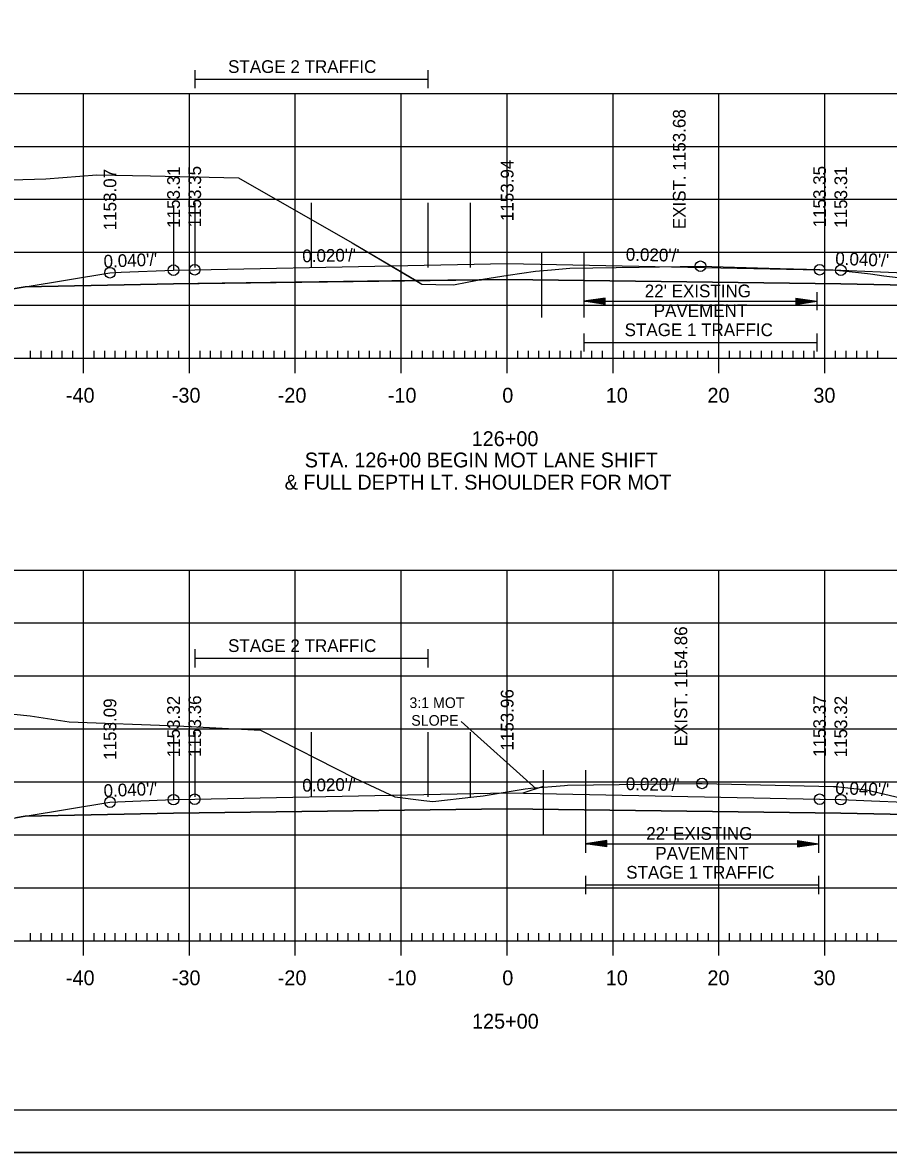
# Model space of a CAD drawing. Extents: x 1322838 to 1324533, y 339903 to 351025.
# Drawn here: x 1323658 to 1323739.7, y 341396.5 to 341503.2 of the extents above; entities that cross this region are included whole.
import ezdxf

# ---------------------------------------------------------------- set-up
doc = ezdxf.new("R2010")
doc.units = 0
for name, color, linetype in [('R_Alt Surface', 7, 'Continuous'), ('R_Axis', 7, 'Continuous'), ('R_Axis Annot', 7, 'Continuous'), ('R_Border', 7, 'Continuous'), ('R_Exist Surface', 7, 'Continuous'), ('R_Fin Surface', 7, 'Continuous'), ('R_Fin Surface Annot', 7, 'Continuous'), ('R_Grid', 7, 'Continuous'), ('R_MOT', 7, 'Continuous'), ('R_No Plot', 7, 'Continuous'), ('R_Xsect Elev', 7, 'Continuous')]:
    doc.layers.add(name, color=color, linetype=linetype)

msp = doc.modelspace()

# ---------------------------------------------------------------- linework, layer by layer
at = {"layer": 'R_Alt Surface'}
for points in [[(1323658.22, 341478.2), (1323672.22, 341478.48), (1323703.72, 341478.91), (1323735.22, 341478.48), (1323749.21, 341478.2)], [(1323658.22, 341428.22), (1323672.22, 341428.5), (1323703.72, 341428.92), (1323735.22, 341428.5), (1323749.21, 341428.22)]]:
    msp.add_lwpolyline(points, dxfattribs=at)
at = {"layer": 'R_Axis'}
for p, q in [((1323663.72, 341470.07), (1323663.72, 341472.87)), ((1323673.72, 341470.07), (1323673.72, 341472.87)), ((1323683.72, 341470.07), (1323683.72, 341472.87)), ((1323693.72, 341470.07), (1323693.72, 341472.87)), ((1323703.72, 341470.07), (1323703.72, 341472.87)), ((1323713.72, 341470.07), (1323713.72, 341472.87)), ((1323723.72, 341470.07), (1323723.72, 341472.87)), ((1323733.72, 341470.07), (1323733.72, 341472.87)), ((1323563.72, 341471.47), (1323843.72, 341471.47)), ((1323658.72, 341471.47), (1323658.72, 341472.17)), ((1323659.72, 341471.47), (1323659.72, 341472.17)), ((1323660.72, 341471.47), (1323660.72, 341472.17)), ((1323661.72, 341471.47), (1323661.72, 341472.17)), ((1323662.72, 341471.47), (1323662.72, 341472.17)), ((1323664.72, 341471.47), (1323664.72, 341472.17)), ((1323665.72, 341471.47), (1323665.72, 341472.17)), ((1323666.72, 341471.47), (1323666.72, 341472.17)), ((1323667.72, 341471.47), (1323667.72, 341472.17)), ((1323668.72, 341471.47), (1323668.72, 341472.17)), ((1323669.72, 341471.47), (1323669.72, 341472.17)), ((1323670.72, 341471.47), (1323670.72, 341472.17)), ((1323671.72, 341471.47), (1323671.72, 341472.17)), ((1323672.72, 341471.47), (1323672.72, 341472.17)), ((1323674.72, 341471.47), (1323674.72, 341472.17)), ((1323675.72, 341471.47), (1323675.72, 341472.17)), ((1323676.72, 341471.47), (1323676.72, 341472.17)), ((1323677.72, 341471.47), (1323677.72, 341472.17)), ((1323678.72, 341471.47), (1323678.72, 341472.17)), ((1323679.72, 341471.47), (1323679.72, 341472.17)), ((1323680.72, 341471.47), (1323680.72, 341472.17)), ((1323681.72, 341471.47), (1323681.72, 341472.17)), ((1323682.72, 341471.47), (1323682.72, 341472.17)), ((1323684.72, 341471.47), (1323684.72, 341472.17)), ((1323685.72, 341471.47), (1323685.72, 341472.17)), ((1323686.72, 341471.47), (1323686.72, 341472.17)), ((1323687.72, 341471.47), (1323687.72, 341472.17)), ((1323688.72, 341471.47), (1323688.72, 341472.17)), ((1323689.72, 341471.47), (1323689.72, 341472.17)), ((1323690.72, 341471.47), (1323690.72, 341472.17)), ((1323691.72, 341471.47), (1323691.72, 341472.17)), ((1323692.72, 341471.47), (1323692.72, 341472.17)), ((1323694.72, 341471.47), (1323694.72, 341472.17)), ((1323695.72, 341471.47), (1323695.72, 341472.17)), ((1323696.72, 341471.47), (1323696.72, 341472.17)), ((1323697.72, 341471.47), (1323697.72, 341472.17)), ((1323698.72, 341471.47), (1323698.72, 341472.17)), ((1323699.72, 341471.47), (1323699.72, 341472.17)), ((1323700.72, 341471.47), (1323700.72, 341472.17)), ((1323701.72, 341471.47), (1323701.72, 341472.17)), ((1323702.72, 341471.47), (1323702.72, 341472.17)), ((1323704.72, 341471.47), (1323704.72, 341472.17)), ((1323705.72, 341471.47), (1323705.72, 341472.17)), ((1323706.72, 341471.47), (1323706.72, 341472.17)), ((1323707.72, 341471.47), (1323707.72, 341472.17)), ((1323708.72, 341471.47), (1323708.72, 341472.17)), ((1323709.72, 341471.47), (1323709.72, 341472.17)), ((1323710.72, 341471.47), (1323710.72, 341472.17)), ((1323711.72, 341471.47), (1323711.72, 341472.17)), ((1323712.72, 341471.47), (1323712.72, 341472.17)), ((1323714.72, 341471.47), (1323714.72, 341472.17)), ((1323715.72, 341471.47), (1323715.72, 341472.17)), ((1323716.72, 341471.47), (1323716.72, 341472.17)), ((1323717.72, 341471.47), (1323717.72, 341472.17)), ((1323718.72, 341471.47), (1323718.72, 341472.17)), ((1323719.72, 341471.47), (1323719.72, 341472.17)), ((1323720.72, 341471.47), (1323720.72, 341472.17)), ((1323721.72, 341471.47), (1323721.72, 341472.17)), ((1323722.72, 341471.47), (1323722.72, 341472.17)), ((1323724.72, 341471.47), (1323724.72, 341472.17)), ((1323725.72, 341471.47), (1323725.72, 341472.17)), ((1323726.72, 341471.47), (1323726.72, 341472.17)), ((1323727.72, 341471.47), (1323727.72, 341472.17)), ((1323728.72, 341471.47), (1323728.72, 341472.17)), ((1323729.72, 341471.47), (1323729.72, 341472.17)), ((1323730.72, 341471.47), (1323730.72, 341472.17)), ((1323731.72, 341471.47), (1323731.72, 341472.17)), ((1323732.72, 341471.47), (1323732.72, 341472.17)), ((1323734.72, 341471.47), (1323734.72, 341472.17)), ((1323735.72, 341471.47), (1323735.72, 341472.17)), ((1323736.72, 341471.47), (1323736.72, 341472.17)), ((1323737.72, 341471.47), (1323737.72, 341472.17)), ((1323738.72, 341471.47), (1323738.72, 341472.17)), ((1323658.72, 341416.47), (1323658.72, 341417.17)), ((1323659.72, 341416.47), (1323659.72, 341417.17)), ((1323660.72, 341416.47), (1323660.72, 341417.17)), ((1323661.72, 341416.47), (1323661.72, 341417.17)), ((1323662.72, 341416.47), (1323662.72, 341417.17)), ((1323663.72, 341415.07), (1323663.72, 341417.87)), ((1323664.72, 341416.47), (1323664.72, 341417.17)), ((1323665.72, 341416.47), (1323665.72, 341417.17)), ((1323666.72, 341416.47), (1323666.72, 341417.17)), ((1323667.72, 341416.47), (1323667.72, 341417.17)), ((1323668.72, 341416.47), (1323668.72, 341417.17)), ((1323669.72, 341416.47), (1323669.72, 341417.17)), ((1323670.72, 341416.47), (1323670.72, 341417.17)), ((1323671.72, 341416.47), (1323671.72, 341417.17)), ((1323672.72, 341416.47), (1323672.72, 341417.17)), ((1323673.72, 341415.07), (1323673.72, 341417.87)), ((1323674.72, 341416.47), (1323674.72, 341417.17)), ((1323675.72, 341416.47), (1323675.72, 341417.17)), ((1323676.72, 341416.47), (1323676.72, 341417.17)), ((1323677.72, 341416.47), (1323677.72, 341417.17)), ((1323678.72, 341416.47), (1323678.72, 341417.17)), ((1323679.72, 341416.47), (1323679.72, 341417.17)), ((1323680.72, 341416.47), (1323680.72, 341417.17)), ((1323681.72, 341416.47), (1323681.72, 341417.17)), ((1323682.72, 341416.47), (1323682.72, 341417.17)), ((1323683.72, 341415.07), (1323683.72, 341417.87)), ((1323684.72, 341416.47), (1323684.72, 341417.17)), ((1323685.72, 341416.47), (1323685.72, 341417.17)), ((1323686.72, 341416.47), (1323686.72, 341417.17)), ((1323687.72, 341416.47), (1323687.72, 341417.17)), ((1323688.72, 341416.47), (1323688.72, 341417.17)), ((1323689.72, 341416.47), (1323689.72, 341417.17)), ((1323690.72, 341416.47), (1323690.72, 341417.17)), ((1323691.72, 341416.47), (1323691.72, 341417.17)), ((1323692.72, 341416.47), (1323692.72, 341417.17)), ((1323693.72, 341415.07), (1323693.72, 341417.87)), ((1323694.72, 341416.47), (1323694.72, 341417.17)), ((1323695.72, 341416.47), (1323695.72, 341417.17)), ((1323696.72, 341416.47), (1323696.72, 341417.17)), ((1323697.72, 341416.47), (1323697.72, 341417.17)), ((1323698.72, 341416.47), (1323698.72, 341417.17)), ((1323699.72, 341416.47), (1323699.72, 341417.17)), ((1323700.72, 341416.47), (1323700.72, 341417.17)), ((1323701.72, 341416.47), (1323701.72, 341417.17)), ((1323702.72, 341416.47), (1323702.72, 341417.17)), ((1323703.72, 341415.07), (1323703.72, 341417.87)), ((1323704.72, 341416.47), (1323704.72, 341417.17)), ((1323705.72, 341416.47), (1323705.72, 341417.17)), ((1323706.72, 341416.47), (1323706.72, 341417.17)), ((1323707.72, 341416.47), (1323707.72, 341417.17)), ((1323708.72, 341416.47), (1323708.72, 341417.17)), ((1323709.72, 341416.47), (1323709.72, 341417.17)), ((1323710.72, 341416.47), (1323710.72, 341417.17)), ((1323711.72, 341416.47), (1323711.72, 341417.17)), ((1323712.72, 341416.47), (1323712.72, 341417.17)), ((1323713.72, 341415.07), (1323713.72, 341417.87)), ((1323714.72, 341416.47), (1323714.72, 341417.17)), ((1323715.72, 341416.47), (1323715.72, 341417.17)), ((1323716.72, 341416.47), (1323716.72, 341417.17)), ((1323717.72, 341416.47), (1323717.72, 341417.17)), ((1323718.72, 341416.47), (1323718.72, 341417.17)), ((1323719.72, 341416.47), (1323719.72, 341417.17)), ((1323720.72, 341416.47), (1323720.72, 341417.17)), ((1323721.72, 341416.47), (1323721.72, 341417.17)), ((1323722.72, 341416.47), (1323722.72, 341417.17)), ((1323723.72, 341415.07), (1323723.72, 341417.87)), ((1323724.72, 341416.47), (1323724.72, 341417.17)), ((1323725.72, 341416.47), (1323725.72, 341417.17)), ((1323726.72, 341416.47), (1323726.72, 341417.17)), ((1323727.72, 341416.47), (1323727.72, 341417.17)), ((1323728.72, 341416.47), (1323728.72, 341417.17)), ((1323729.72, 341416.47), (1323729.72, 341417.17)), ((1323730.72, 341416.47), (1323730.72, 341417.17)), ((1323731.72, 341416.47), (1323731.72, 341417.17)), ((1323732.72, 341416.47), (1323732.72, 341417.17)), ((1323733.72, 341415.07), (1323733.72, 341417.87)), ((1323734.72, 341416.47), (1323734.72, 341417.17)), ((1323735.72, 341416.47), (1323735.72, 341417.17)), ((1323736.72, 341416.47), (1323736.72, 341417.17)), ((1323737.72, 341416.47), (1323737.72, 341417.17)), ((1323738.72, 341416.47), (1323738.72, 341417.17)), ((1323563.72, 341416.47), (1323843.72, 341416.47))]:
    msp.add_line(p, q, dxfattribs=at)
at = {"layer": 'R_Axis Annot'}
for p, q in [((1323674.22, 341498.66), (1323674.22, 341496.96)), ((1323696.22, 341498.66), (1323696.22, 341496.96)), ((1323674.22, 341497.81), (1323696.22, 341497.81)), ((1323710.97, 341477.7), (1323710.97, 341475.99)), ((1323712.97, 341477.15), (1323710.97, 341476.85)), ((1323712.97, 341476.55), (1323710.97, 341476.85)), ((1323710.97, 341476.85), (1323732.97, 341476.85)), ((1323712.97, 341477.1), (1323711.31, 341476.85)), ((1323712.97, 341476.6), (1323711.31, 341476.85)), ((1323712.97, 341477.05), (1323711.65, 341476.85)), ((1323712.97, 341476.65), (1323711.65, 341476.85)), ((1323712.97, 341477), (1323711.98, 341476.85)), ((1323712.97, 341476.7), (1323711.98, 341476.85)), ((1323712.97, 341476.94), (1323712.32, 341476.85)), ((1323712.97, 341476.75), (1323712.32, 341476.85)), ((1323712.97, 341476.89), (1323712.66, 341476.85)), ((1323712.97, 341476.8), (1323712.66, 341476.85)), ((1323712.97, 341476.55), (1323712.97, 341477.15)), ((1323730.97, 341477.15), (1323732.97, 341476.85)), ((1323730.97, 341477.15), (1323730.97, 341476.55)), ((1323730.97, 341477.1), (1323732.64, 341476.85)), ((1323730.97, 341477.05), (1323732.3, 341476.85)), ((1323730.97, 341477), (1323731.96, 341476.85)), ((1323730.97, 341476.94), (1323731.62, 341476.85)), ((1323730.97, 341476.89), (1323731.29, 341476.85)), ((1323730.97, 341476.55), (1323732.97, 341476.85)), ((1323730.97, 341476.75), (1323731.62, 341476.85)), ((1323730.97, 341476.65), (1323732.3, 341476.85)), ((1323730.97, 341476.6), (1323732.64, 341476.85)), ((1323730.97, 341476.7), (1323731.96, 341476.85)), ((1323730.97, 341476.8), (1323731.29, 341476.85)), ((1323732.97, 341477.7), (1323732.97, 341475.99)), ((1323710.97, 341473.81), (1323710.97, 341472.1)), ((1323732.97, 341473.81), (1323732.97, 341472.1)), ((1323710.97, 341472.96), (1323732.97, 341472.96)), ((1323674.22, 341443.99), (1323674.22, 341442.28)), ((1323696.22, 341443.99), (1323696.22, 341442.28)), ((1323674.22, 341443.14), (1323696.22, 341443.14)), ((1323711.12, 341426.48), (1323711.12, 341424.77)), ((1323713.12, 341425.92), (1323711.12, 341425.62)), ((1323713.12, 341425.32), (1323711.12, 341425.62)), ((1323711.12, 341425.62), (1323733.12, 341425.62)), ((1323713.12, 341425.87), (1323711.46, 341425.62)), ((1323713.12, 341425.37), (1323711.46, 341425.62)), ((1323713.12, 341425.82), (1323711.8, 341425.62)), ((1323713.12, 341425.43), (1323711.8, 341425.62)), ((1323713.12, 341425.77), (1323712.13, 341425.62)), ((1323713.12, 341425.48), (1323712.13, 341425.62)), ((1323713.12, 341425.72), (1323712.47, 341425.62)), ((1323713.12, 341425.53), (1323712.47, 341425.62)), ((1323713.12, 341425.67), (1323712.81, 341425.62)), ((1323713.12, 341425.58), (1323712.81, 341425.62)), ((1323713.12, 341425.32), (1323713.12, 341425.92)), ((1323731.12, 341425.92), (1323733.12, 341425.62)), ((1323731.12, 341425.92), (1323731.12, 341425.32)), ((1323731.12, 341425.87), (1323732.79, 341425.62)), ((1323731.12, 341425.82), (1323732.44, 341425.62)), ((1323731.12, 341425.77), (1323732.11, 341425.62)), ((1323731.12, 341425.72), (1323731.77, 341425.62)), ((1323731.12, 341425.67), (1323731.44, 341425.62)), ((1323731.12, 341425.32), (1323733.12, 341425.62)), ((1323731.12, 341425.53), (1323731.77, 341425.62)), ((1323731.12, 341425.43), (1323732.44, 341425.62)), ((1323731.12, 341425.37), (1323732.79, 341425.62)), ((1323731.12, 341425.48), (1323732.11, 341425.62)), ((1323731.12, 341425.58), (1323731.44, 341425.62)), ((1323733.12, 341426.48), (1323733.12, 341424.77)), ((1323711.12, 341422.59), (1323711.12, 341420.88)), ((1323733.12, 341422.59), (1323733.12, 341420.88)), ((1323711.12, 341421.74), (1323733.12, 341421.74))]:
    msp.add_line(p, q, dxfattribs=at)
at = {"layer": 'R_Border'}
msp.add_line((1323861.9, 341400.47), (1323545.72, 341400.47), dxfattribs=at)
at = {"layer": 'R_Exist Surface'}
for points in [[(1323652.58, 341488.17), (1323660.17, 341488.39), (1323664.98, 341488.78), (1323670.03, 341488.68), (1323678.34, 341488.49), (1323689.1, 341482.37), (1323695.67, 341478.47), (1323697, 341478.43), (1323698.64, 341478.41), (1323699.94, 341478.66), (1323701.43, 341478.93), (1323703.83, 341479.3), (1323706.41, 341479.68), (1323707.9, 341479.81), (1323709.63, 341479.96), (1323716.18, 341480.06), (1323721.97, 341480.15), (1323729.49, 341479.94), (1323734.5, 341479.8), (1323736.62, 341479.58), (1323738.02, 341479.43), (1323739.28, 341479.26), (1323741.18, 341479.03)], [(1323653.12, 341438.27), (1323658.69, 341437.69), (1323662.37, 341437.13), (1323672.61, 341436.77), (1323680.42, 341436.36), (1323689.33, 341431.83), (1323693.13, 341430.05), (1323695.84, 341429.71), (1323696.7, 341429.6), (1323700.57, 341430.06), (1323701.44, 341430.15), (1323705.41, 341430.8), (1323705.96, 341430.89), (1323709.13, 341431.14), (1323709.43, 341431.17), (1323721.64, 341431.32), (1323722.12, 341431.32), (1323734.52, 341431.02), (1323734.76, 341431.02), (1323737.58, 341430.73), (1323737.6, 341430.72), (1323737.77, 341430.68), (1323741.39, 341429.85)]]:
    msp.add_lwpolyline(points, dxfattribs=at)
at = {"layer": 'R_Fin Surface'}
for points in [[(1323607.85, 341487.99), (1323626.65, 341481.72), (1323644.22, 341475.87), (1323649.14, 341476.69), (1323658.22, 341478.2), (1323666.22, 341479.54), (1323667.27, 341479.58), (1323672.22, 341479.78), (1323674.22, 341479.82), (1323692.76, 341480.19), (1323703.72, 341480.41), (1323733.22, 341479.82), (1323735.22, 341479.78), (1323741.22, 341479.54), (1323744.94, 341478.92), (1323749.21, 341478.2), (1323752.69, 341477.62), (1323763.22, 341475.87), (1323775.53, 341479.97), (1323786.78, 341483.72)], [(1323597.09, 341441.6), (1323597.09, 341441.59), (1323644.22, 341425.89), (1323657.29, 341428.07), (1323658.22, 341428.22), (1323666.22, 341429.55), (1323668.39, 341429.64), (1323672.22, 341429.79), (1323674.22, 341429.83), (1323695.85, 341430.27), (1323703.72, 341430.42), (1323733.22, 341429.83), (1323733.28, 341429.83), (1323735.22, 341429.79), (1323738.12, 341429.68), (1323741.22, 341429.55), (1323743.21, 341429.22), (1323749.21, 341428.22), (1323763.17, 341425.89), (1323763.22, 341425.89), (1323763.27, 341425.9), (1323775.11, 341429.85)]]:
    msp.add_lwpolyline(points, dxfattribs=at)
at = {"layer": 'R_Grid'}
for p, q in [((1323563.72, 341496.47), (1323843.72, 341496.47)), ((1323663.72, 341471.47), (1323663.72, 341496.47)), ((1323673.72, 341471.47), (1323673.72, 341496.47)), ((1323683.72, 341471.47), (1323683.72, 341496.47)), ((1323693.72, 341471.47), (1323693.72, 341496.47)), ((1323703.72, 341471.47), (1323703.72, 341496.47)), ((1323713.72, 341471.47), (1323713.72, 341496.47)), ((1323723.72, 341471.47), (1323723.72, 341496.47)), ((1323733.72, 341471.47), (1323733.72, 341496.47)), ((1323563.72, 341491.47), (1323843.72, 341491.47)), ((1323563.72, 341486.47), (1323843.72, 341486.47)), ((1323563.72, 341481.47), (1323843.72, 341481.47)), ((1323563.72, 341476.47), (1323843.72, 341476.47)), ((1323563.72, 341471.47), (1323843.72, 341471.47)), ((1323563.72, 341451.47), (1323843.72, 341451.47)), ((1323663.72, 341416.47), (1323663.72, 341451.47)), ((1323673.72, 341416.47), (1323673.72, 341451.47)), ((1323683.72, 341416.47), (1323683.72, 341451.47)), ((1323693.72, 341416.47), (1323693.72, 341451.47)), ((1323703.72, 341416.47), (1323703.72, 341451.47)), ((1323713.72, 341416.47), (1323713.72, 341451.47)), ((1323723.72, 341416.47), (1323723.72, 341451.47)), ((1323733.72, 341416.47), (1323733.72, 341451.47)), ((1323563.72, 341446.47), (1323843.72, 341446.47)), ((1323563.72, 341441.47), (1323843.72, 341441.47)), ((1323563.72, 341436.47), (1323843.72, 341436.47)), ((1323563.72, 341431.47), (1323843.72, 341431.47)), ((1323563.72, 341426.47), (1323843.72, 341426.47)), ((1323563.72, 341421.47), (1323843.72, 341421.47)), ((1323563.72, 341416.47), (1323843.72, 341416.47))]:
    msp.add_line(p, q, dxfattribs=at)
at = {"layer": 'R_MOT'}
for p, q in [((1323706.47, 341430.81), (1323699.37, 341437.18)), ((1323707.12, 341431.03), (1323705.21, 341430.39))]:
    msp.add_line(p, q, dxfattribs=at)
at = {"layer": 'R_No Plot'}
for p, q in [((1323672.22, 341485.88), (1323672.22, 341479.78)), ((1323674.22, 341486.14), (1323674.22, 341480.03)), ((1323685.22, 341486.14), (1323685.22, 341480.03)), ((1323696.22, 341486.14), (1323696.22, 341480.03)), ((1323700.22, 341486.14), (1323700.22, 341480.03)), ((1323706.97, 341481.41), (1323706.97, 341475.3)), ((1323710.97, 341481.41), (1323710.97, 341475.3)), ((1323672.22, 341435.9), (1323672.22, 341429.79)), ((1323674.22, 341436.16), (1323674.22, 341430.05)), ((1323685.22, 341436.16), (1323685.22, 341430.05)), ((1323696.22, 341436.16), (1323696.22, 341430.05)), ((1323700.22, 341436.16), (1323700.22, 341430.05)), ((1323707.12, 341432.58), (1323707.12, 341426.47)), ((1323711.12, 341432.58), (1323711.12, 341426.47)), ((1323533.31, 341396.49), (1323866.65, 341396.49))]:
    msp.add_line(p, q, dxfattribs=at)
for points in [[(1323533.31, 341609.82), (1323866.65, 341609.82), (1323866.65, 341396.49), (1323533.31, 341396.49)], [(1323779.64, 341605.93), (1323799.26, 341605.93), (1323799.26, 341596.05), (1323815.37, 341596.05), (1323838.57, 341596.05), (1323838.57, 341563.38), (1323861.77, 341563.38), (1323861.9, 341400.47), (1323545.72, 341400.47), (1323545.72, 341605.93)], [(1323607.85, 341487.99), (1323631.91, 341488.09), (1323652.58, 341488.17), (1323660.17, 341488.39), (1323664.98, 341488.78), (1323670.03, 341488.68), (1323678.34, 341488.49), (1323689.1, 341482.37), (1323695.14, 341478.79), (1323672.22, 341478.48), (1323658.22, 341478.2), (1323649.14, 341476.69), (1323644.22, 341475.87), (1323626.65, 341481.72)], [(1323695.14, 341478.79), (1323695.67, 341478.47), (1323697, 341478.43), (1323698.64, 341478.41), (1323699.94, 341478.66), (1323701.09, 341478.87)]]:
    msp.add_lwpolyline(points, close=True, dxfattribs=at)
for points in [[(1323749.21, 341478.2), (1323735.22, 341478.48), (1323703.72, 341478.91), (1323701.09, 341478.87), (1323701.43, 341478.93), (1323703.83, 341479.3), (1323706.41, 341479.68), (1323707.9, 341479.81), (1323709.63, 341479.96), (1323716.18, 341480.06), (1323721.97, 341480.15), (1323729.49, 341479.94), (1323734.5, 341479.8), (1323736.62, 341479.58), (1323738.02, 341479.43), (1323739.28, 341479.26), (1323741.18, 341479.03)], [(1323653.12, 341438.27), (1323658.69, 341437.69), (1323662.37, 341437.13), (1323672.61, 341436.77), (1323680.42, 341436.36), (1323689.33, 341431.83), (1323693.13, 341430.05), (1323695.84, 341429.71), (1323696.7, 341429.6), (1323700.57, 341430.06), (1323701.44, 341430.15), (1323705.41, 341430.8), (1323705.96, 341430.89), (1323709.13, 341431.14), (1323709.43, 341431.17), (1323721.64, 341431.32), (1323722.12, 341431.32), (1323734.52, 341431.02), (1323734.76, 341431.02), (1323737.58, 341430.73), (1323737.6, 341430.72), (1323737.77, 341430.68), (1323741.39, 341429.85)], [(1323749.21, 341428.22), (1323735.22, 341428.5), (1323703.72, 341428.92), (1323672.22, 341428.5), (1323658.22, 341428.22), (1323657.29, 341428.07)]]:
    msp.add_lwpolyline(points, dxfattribs=at)
for centre in [(1323666.22, 341479.54), (1323666.22, 341479.54), (1323672.22, 341479.78), (1323672.22, 341479.78), (1323674.22, 341479.82), (1323674.22, 341479.82), (1323721.97, 341480.15), (1323733.22, 341479.82), (1323733.22, 341479.82), (1323735.22, 341479.78), (1323735.22, 341479.78), (1323722.12, 341431.32), (1323666.22, 341429.55), (1323666.22, 341429.55), (1323672.22, 341429.79), (1323672.22, 341429.79), (1323674.22, 341429.83), (1323674.22, 341429.83), (1323733.22, 341429.83), (1323733.22, 341429.83), (1323735.22, 341429.79), (1323735.22, 341429.79)]:
    msp.add_circle(centre, 0.5, dxfattribs=at)

# ---------------------------------------------------------------- texts
at = {"layer": 'R_Axis Annot'}
for s, height, p in [('STAGE 2 TRAFFIC', 1.2, (1323677.37, 341498.4)), ("22' EXISTING ", 1.2, (1323716.71, 341477.22)), ('PAVEMENT', 1.2, (1323717.56, 341475.36)), ('STAGE 1 TRAFFIC', 1.2, (1323714.81, 341473.55)), ('-40', 1.4, (1323662.06, 341467.27)), ('-30', 1.4, (1323672.06, 341467.27)), ('-20', 1.4, (1323682.06, 341467.27)), ('-10', 1.4, (1323692.45, 341467.27)), ('0', 1.4, (1323703.26, 341467.27)), ('10', 1.4, (1323713.03, 341467.27)), ('20', 1.4, (1323722.63, 341467.27)), ('30', 1.4, (1323732.63, 341467.27)), ('126+00', 1.4, (1323700.37, 341463.17)), ('STA. 126+00 BEGIN MOT LANE SHIFT ', 1.4, (1323684.61, 341461.16)), ('& FULL DEPTH LT. SHOULDER FOR MOT', 1.4, (1323682.71, 341459.06)), ('STAGE 2 TRAFFIC', 1.2, (1323677.37, 341443.73)), ("22' EXISTING ", 1.2, (1323716.85, 341426)), ('PAVEMENT', 1.2, (1323717.71, 341424.13)), ('STAGE 1 TRAFFIC', 1.2, (1323714.96, 341422.33)), ('-40', 1.4, (1323662.06, 341412.27)), ('-30', 1.4, (1323672.06, 341412.27)), ('-20', 1.4, (1323682.06, 341412.27)), ('-10', 1.4, (1323692.45, 341412.27)), ('0', 1.4, (1323703.26, 341412.27)), ('10', 1.4, (1323713.03, 341412.27)), ('20', 1.4, (1323722.63, 341412.27)), ('30', 1.4, (1323732.63, 341412.27)), ('125+00', 1.4, (1323700.4, 341408.17))]:
    msp.add_text(s, height=height, dxfattribs=at).set_placement(p)
at = {"layer": 'R_Fin Surface Annot'}
for s, rotation, p in [('1153.31', 90, (1323672.82, 341483.78)), ('1153.35', 90, (1323674.82, 341483.82)), ('1153.94', 90, (1323704.32, 341484.41)), ('1153.35', 90, (1323733.82, 341483.82)), ('1153.31', 90, (1323735.82, 341483.78)), ('1153.07', 90, (1323666.82, 341483.54)), ("0.040'/'", 2.2906, (1323665.64, 341480.01)), ("0.020'/'", 1.1458, (1323684.39, 341480.52)), ("0.020'/'", 358.8542, (1323714.91, 341480.68)), ("0.040'/'", 357.7094, (1323734.68, 341480.3)), ('1153.32', 90, (1323672.82, 341433.79)), ('1153.36', 90, (1323674.82, 341433.83)), ('1153.96', 90, (1323704.32, 341434.42)), ('1153.37', 90, (1323733.82, 341433.83)), ('1153.32', 90, (1323735.82, 341433.79)), ('1153.09', 90, (1323666.82, 341433.55)), ("0.020'/'", 1.1458, (1323684.39, 341430.54)), ("0.020'/'", 358.8542, (1323714.91, 341430.7)), ("0.040'/'", 2.2906, (1323665.64, 341430.03)), ("0.040'/'", 357.7094, (1323734.68, 341430.32))]:
    msp.add_text(s, height=1.2, rotation=rotation, dxfattribs=at).set_placement(p)
at = {"layer": 'R_MOT'}
for s, p in [('3:1 MOT', (1323694.49, 341438.44)), ('SLOPE', (1323694.67, 341436.77))]:
    msp.add_text(s, height=1, dxfattribs=at).set_placement(p)
at = {"layer": 'R_Xsect Elev'}
for s, p in [('EXIST. 1153.68', (1323720.57, 341483.65)), ('EXIST. 1154.86', (1323720.72, 341434.82))]:
    msp.add_text(s, height=1.2, rotation=90, dxfattribs=at).set_placement(p)

doc.saveas('drawing.dxf')
